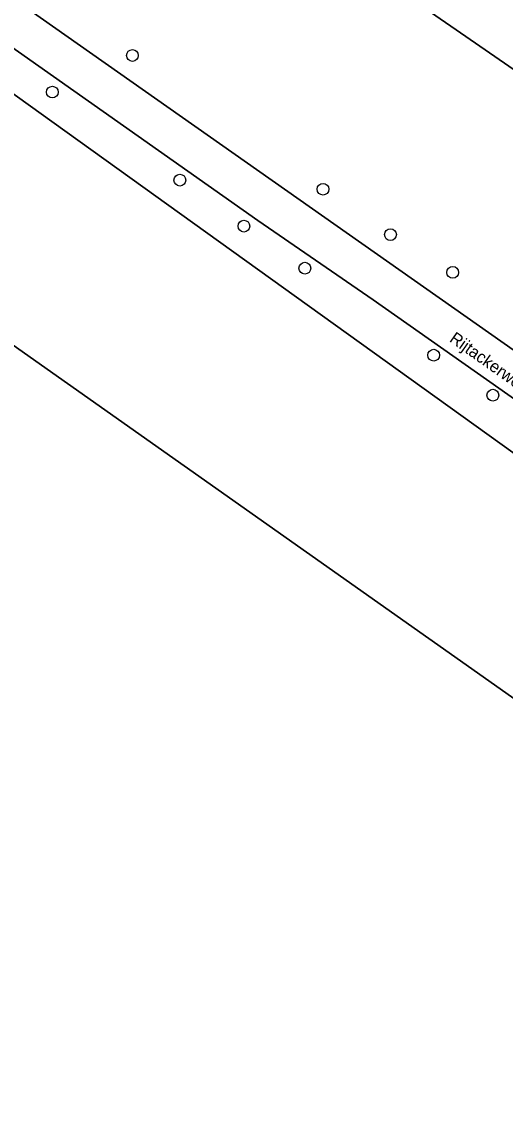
# Model space of a CAD drawing. Extents: x 155209 to 156748, y 385356 to 388487.
# Drawn here: x 156106.4 to 156146.5, y 386032 to 386122.9 of the extents above; entities that cross this region are included whole.
import ezdxf

# ---------------------------------------------------------------- set-up
doc = ezdxf.new("R2010")
doc.units = 0
for name, color, linetype in [('IMGEO_Berm_groen', 7, 'Continuous'), ('IMGEO_Boom', 7, 'Continuous'), ('IMGEO_Loofbos', 7, 'Continuous'), ('IMGEO_Openbare_ruimte_label', 7, 'Continuous'), ('IMGEO_Parkeervlak_gesloten', 7, 'Continuous'), ('IMGEO_Rijbaan_lokaal_gesloten', 7, 'Continuous')]:
    doc.layers.add(name, color=color, linetype=linetype)

msp = doc.modelspace()

# ---------------------------------------------------------------- linework, layer by layer
at = {"layer": 'IMGEO_Berm_groen'}
for points in [[(156135.525, 386099.824), (156125.947, 386106.412), (156097.821, 386126.258), (156097.061, 386125.693), (156097.328, 386122.883), (156148.229, 386086.381)], [(156177.592, 386068.133), (156199.703, 386052.574), (156208.507, 386046.262), (156209.236, 386046.841), (156203.462, 386051.763), (156174.479, 386072.454), (156135.525, 386099.824)]]:
    msp.add_lwpolyline(points, dxfattribs=at)
at = {"layer": 'IMGEO_Boom'}
for centre in [(156115.546, 386120.113), (156108.897, 386117.073), (156119.483, 386109.761), (156131.375, 386109.006), (156124.802, 386105.941), (156136.974, 386105.237), (156129.867, 386102.45), (156142.144, 386102.098), (156140.565, 386095.223), (156145.478, 386091.902)]:
    msp.add_circle(centre, 0.489, dxfattribs=at)
at = {"layer": 'IMGEO_Loofbos'}
msp.add_lwpolyline([(156086.245, 386160.941), (156083.539, 386162.841), (156082.842, 386161.532), (156081.654, 386159.304), (156074.85, 386146.487), (156076.416, 386145.394), (156078.082, 386144.223), (156148.477, 386094.745), (156151.385, 386092.684), (156153.847, 386090.939), (156156.709, 386094.126), (156162.572, 386100.654), (156166.855, 386105.424), (156156.688, 386112.431), (156153.599, 386114.559), (156143.245, 386121.695)], close=True, dxfattribs=at)
for points in [[(156097.328, 386122.883), (156098.871, 386106.675), (156095.929, 386102.882), (156099.957, 386100.042), (156160.003, 386057.7), (156157.509, 386054.166), (156161.542, 386051.343), (156165.108, 386055.996), (156179.962, 386045.422), (156184.53, 386042.685)], [(156199.002, 386045.658), (156201.611, 386049.586), (156176.599, 386066.747), (156171.777, 386070.098), (156148.229, 386086.381), (156097.328, 386122.883)]]:
    msp.add_lwpolyline(points, dxfattribs=at)
at = {"layer": 'IMGEO_Parkeervlak_gesloten'}
msp.add_lwpolyline([(156160.003, 386057.7), (156099.957, 386100.042), (156097.486, 386096.491), (156093.457, 386099.385), (156081.423, 386082.358), (156073.913, 386071.732), (156058.168, 386049.454), (156094.05, 386024.137), (156103.891, 386017.194), (156126.188, 386001.462), (156126.295, 386001.387), (156154.838, 386041.842), (156161.542, 386051.343), (156157.509, 386054.166)], close=True, dxfattribs=at)
at = {"layer": 'IMGEO_Rijbaan_lokaal_gesloten'}
for points in [[(156079.419, 386165.495), (156083.539, 386162.841), (156086.245, 386160.941), (156143.245, 386121.695), (156153.599, 386114.559), (156156.688, 386112.431), (156166.855, 386105.424), (156212.41, 386074.028), (156213.347, 386073.3)], [(156097.821, 386126.258), (156125.947, 386106.412), (156135.525, 386099.824), (156174.479, 386072.454), (156203.462, 386051.763), (156209.236, 386046.841), (156212.064, 386049.111), (156212.178, 386049.201), (156205.144, 386054.589), (156153.847, 386090.939), (156151.385, 386092.684), (156148.477, 386094.745), (156078.082, 386144.223)]]:
    msp.add_lwpolyline(points, dxfattribs=at)

# ---------------------------------------------------------------- texts
at = {"layer": 'IMGEO_Openbare_ruimte_label'}
msp.add_text('Rijtackerweg', height=1, rotation=324.68879, dxfattribs=at).set_placement((156141.804, 386096.412))

doc.saveas('drawing.dxf')
